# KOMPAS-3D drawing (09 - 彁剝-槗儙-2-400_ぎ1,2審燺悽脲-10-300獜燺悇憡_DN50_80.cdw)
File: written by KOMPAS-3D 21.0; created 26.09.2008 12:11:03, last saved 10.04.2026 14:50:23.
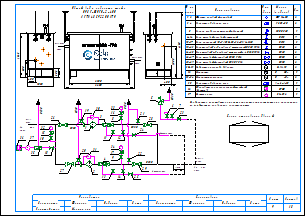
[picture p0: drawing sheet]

Sheets 1-2: A3, landscape

Document properties: Наименование: Макро:21; Автор: RaskoAdmin; Форматы листов документа: 2xA3; Полное имя файла: \\UR38nt01\Departments\КТО\КБ ПУРДГ\Заявки\Прайс-лист на типовые шкафы ГРПШ\ПРДГ_стандарт_20_03_2026\ПРДГ с РДСК\ПРДГ-ШУГО-2-400_до1,2МПа_Рвых-10-300кПа_РДСК_DN50_80.cdw

Title block, sheet 1: Наименование: Пункт учета газа / ПУГ-Ш-400-Р / ЛГТИ.485922.001ТУ; designation: ЛГТИ.03.4411141; sheet number: 1; Количество листов документа: 2; organisation: ООО "ЭЛЬСТЕР Газэлектроника"; Форматы листов документа: A3; stored path: C:\Рабочие документы\Компас\ПУГ\Схема.cdw; Разработал: Устинов; Проверил: Кошкин; Утвердил: Кошкин
Title block, sheet 2: sheet number: 2; stored path: D:\Рабочие документы\Заявки\ПУРДГ\ПУРДГ-ШУЭО-2-100-Р 4411220.cdw; designation, second copy: ЛГТИ.03.4411141-

Views: Вид 1, Вид 2
Referenced files: wcvoit.frw
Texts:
  Normal
  Вход
  газа
  PDI
  Выход
  Р=     кПа
  DN80
  DN50
  DN20
  Импульс DN20
  ≥5DN
  HYSWLongFangSong
  № на
  схеме
  Усл.
  обозн.
  Марка
  (модель)
  Кол.
  Фильтр газовый фланцевый
  ФГ 16-50
  Регулятор давления газа
  РДCК-50
  Клапан предохранительный сбросной
  КПС DN20
  Кран шаровой газовый латунный
  DN15
  Кран кнопочный VE-РАСКО-НЗ-1,6-G1/2-М20
  Кран шаровой "под приварку" штуцерный DN20 PN16
  Кран шаровой "под приварку" штуцерный п/п DN20 PN16
  Кран шаровой фланцевый DN50 PN16
  Кран шаровой фланцевый DN80 PN16
  Индикатор перепада давления
  Delta 15
  Манометр
  Манометр-напоромер
  0...     МПа
  0...     кПа
  Обогреватель газогорелочный шкафной
  (Эльтон")
  Счетчик газа
  Venio-A-15
  ОГШН
  BK-G1,6
  Общий вид и габариты шкафа
  ПРДГ-ШУГО-2-400
  Выход газа
  Вход газа
  Схема открывания дверей
  Р=        МПа
  logo-rasko-ge.png
  Предприятие изготовитель может заменять комплектующие на аналогичные,
  не ухудшающие заявленных характеристик.
  Должность
  Конструктор
  Фамилия
  Подпись
  Дата
  Согласовано
  Максимкин
  Лист
  Листов
  POLYLINE_STYLE_0.18_RGB_0_0_0
  POLYLINE_STYLE_0.50_RGB_0_0_0
  POLYLINE_STYLE_0.34_RGB_0_0_0
  PHANTOM_RGB_0_0_0_SC_1_THICK_0.18
  K5LT_THIN_RGB_0_0_0_THICK_0.18
  K5LT32769_RGB_0_0_0_THICK_0.18
  K5LT12_RGB_0_0_0_SC_1_THICK_0.18
  K5LT_DASHED_RGB_0_0_0_SC_1_THICK_0.18
  ACISOTGL_RGB_0_0_0_SC_0.8_THICK_0.25
  CONTINUOUS_RGB_0_127_31_THICK_0.3
  CONTINUOUS_RGB_0_0_255_THICK_0.35
  CONTINUOUS_RGB_255_0_0_THICK_0.35
  POLYLINE_STYLE_0.25_RGB_0_0_0
  CONTINUOUS_RGB_0_0_0_THICK_0.5
  POLYLINE_STYLE_0.35_RGB_0_0_255
  CONTINUOUS_RGB_0_0_0_THICK_0.4
  CONTINUOUS_RGB_0_0_0_THICK_0.35
  Без оформления
Dimensions and other numbers on the sheet: 1; 2; 3; 4; 5; 10; 27; 28; 29; 23; 8; 12; 18; 19; 20; 21; 22; 25; 24; 30; 31; 15; 16; 35; 36; 26; 6; 7; 11; 14; 13; 33; 1, 2; 3, 4; 6-14; 9; 15-17; 18-23; 24-25; 26-27; 28-29; 30-31; 32; 33-34; 37; 400; 1050; 500; 305; 2300; 1565; 2600; 17; 34; 1000; 4130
